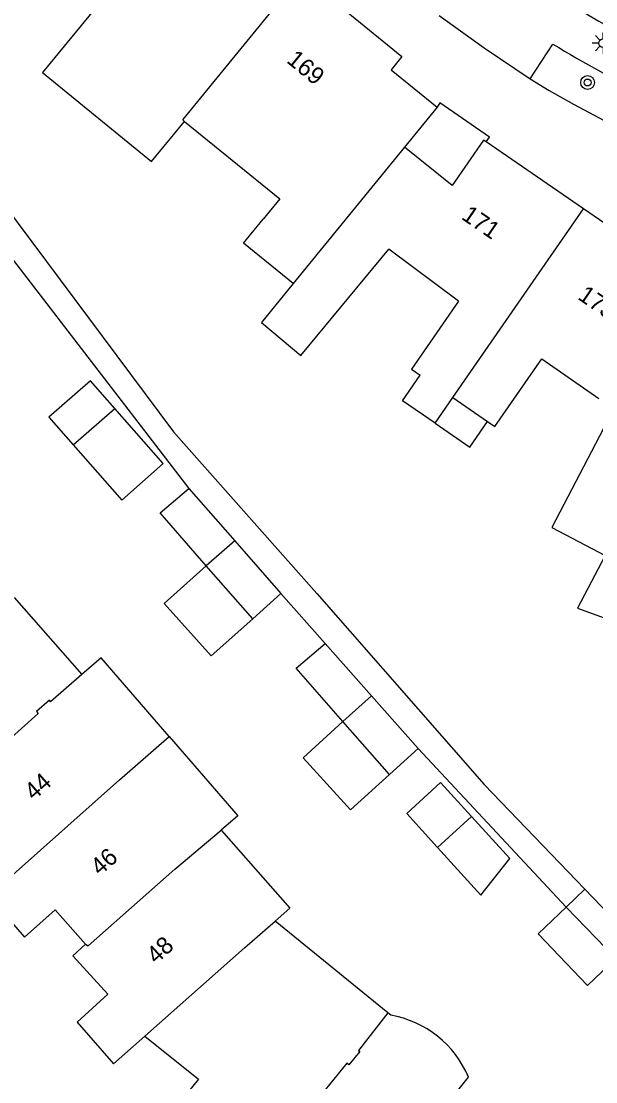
# Model space of a CAD drawing. Extents: x 126000 to 131009, y 393000 to 395500.
# Drawn here: x 130518.8 to 130552.1, y 394946.8 to 395008.4 of the extents above; entities that cross this region are included whole.
import ezdxf

# ---------------------------------------------------------------- set-up
doc = ezdxf.new("R2010")
doc.units = 0
for name, color, linetype in [('gg-afsc-erfafscheiding', 7, 'Continuous'), ('gg-anno-huisnummerreeks BGT', 7, 'Continuous'), ('gg-bbg-gedigitaliseerde bebouwing', 7, 'Continuous'), ('gg-bbg-gedigitaliseerde bijgebouw', 7, 'Continuous'), ('gg-bbg-hoofdgebouw', 7, 'Continuous'), ('gg-bbg-luifel en loopbrug', 7, 'Continuous'), ('gg-bbg-tussenscheiding', 7, 'Continuous'), ('gg-knt-verharding', 7, 'Continuous'), ('gt-grn-groengrens', 7, 'Continuous'), ('gt-symb-boom', 7, 'Continuous'), ('gt-symb-lichtmast', 7, 'Continuous')]:
    doc.layers.add(name, color=color, linetype=linetype)

# ---------------------------------------------------------------- blocks, each defined once
blk = doc.blocks.new('gt0-BOOM')
at = {"layer": 'gt-symb-boom'}
for radius in [0.4, 0.2]:
    blk.add_circle((0, 0), radius, dxfattribs=at)
blk = doc.blocks.new('gt0-LMAST')
at = {"layer": 'gt-symb-lichtmast'}
for p, q in [((-0.005, 0.246), (-0.005, 0.621)), ((-0.182, 0.173), (-0.447, 0.438)), ((0.172, 0.173), (0.437, 0.438)), ((-0.255, -0.004), (-0.63, -0.004)), ((-0.182, -0.181), (-0.447, -0.446)), ((-0.005, -0.254), (-0.005, -0.629)), ((0.437, -0.446), (0.172, -0.181)), ((0.245, -0.004), (0.62, -0.004))]:
    blk.add_line(p, q, dxfattribs=at)
blk.add_circle((-0.005, -0.004), 0.25, dxfattribs=at)

msp = doc.modelspace()

# ---------------------------------------------------------------- linework, layer by layer
at = {"layer": 'gg-afsc-erfafscheiding'}
for p, q in [((130518.346, 394994.504), (130528.53, 394981.27)), ((130533.87, 394975.19), (130536.44, 394972.29)), ((130541.82, 394966.18), (130550.41, 394956.98))]:
    msp.add_line(p, q, dxfattribs=at)
msp.add_lwpolyline([(130516.105, 395000), (130527.64, 394984.57), (130535.94, 394975.18), (130545.66, 394964.1), (130551.495, 394958.025)], dxfattribs=at)
at = {"layer": 'gg-bbg-gedigitaliseerde bebouwing'}
for p, q in [((130544.17, 394992.15), (130540.12, 394995.16)), ((130542.822, 394985.06), (130543.849, 394986.548)), ((130543.849, 394986.548), (130545.855, 394985.166)), ((130518.391, 394974.945), (130522.308, 394970.49)), ((130540.074, 394950.844), (130533.525, 394956.169)), ((130540.238, 394950.71), (130540.074, 394950.844)), ((130542.346, 394944.153), (130544.751, 394947.111))]:
    msp.add_line(p, q, dxfattribs=at)
for points in [[(130520.035, 395005.423), (130526.358, 395000.255), (130528.27, 395002.58)], [(130528.27, 395002.58), (130533.8, 394998.09), (130532.84, 394996.91)], [(130534.583, 394993.171), (130531.704, 394995.514), (130532.84, 394996.91)], [(130534.583, 394993.171), (130532.73, 394990.91), (130535.03, 394988.99), (130540.12, 394995.16)], [(130544.17, 394992.15), (130541.44, 394988.21), (130541.946, 394987.861)], [(130545.855, 394985.166), (130546.27, 394984.88), (130549, 394988.8), (130552.32, 394986.5)], [(130542.822, 394985.06), (130540.92, 394986.372), (130541.946, 394987.861)], [(130527.375, 394966.888), (130523.428, 394971.457), (130522.308, 394970.49)], [(130527.375, 394966.888), (130531.358, 394962.279), (130530.393, 394961.445)], [(130530.393, 394961.445), (130534.383, 394956.927), (130533.525, 394956.169)]]:
    msp.add_lwpolyline(points, dxfattribs=at)
msp.add_arc((130539.183, 394944.759), 6.044, 22.90496, 79.95214, dxfattribs=at)
at = {"layer": 'gg-bbg-gedigitaliseerde bijgebouw'}
for p, q in [((130521.815, 394983.809), (130524.228, 394985.91)), ((130527.036, 394982.718), (130524.228, 394985.91)), ((130528.53, 394981.27), (130531.192, 394978.239)), ((130531.192, 394978.239), (130533.87, 394975.19)), ((130532.23, 394973.72), (130529.537, 394976.793)), ((130533.87, 394975.19), (130532.23, 394973.72)), ((130536.44, 394972.29), (130539.13, 394969.235)), ((130539.13, 394969.235), (130541.82, 394966.18)), ((130540.16, 394964.67), (130537.46, 394967.755)), ((130541.82, 394966.18), (130540.16, 394964.67)), ((130544.928, 394962.234), (130542.956, 394960.44)), ((130550.41, 394956.98), (130553.29, 394953.99))]:
    msp.add_line(p, q, dxfattribs=at)
for points in [[(130553.277, 394986.099), (130549.58, 394979.02), (130552.68, 394977.38)], [(130521.815, 394983.809), (130524.632, 394980.604), (130527.036, 394982.718)], [(130529.537, 394976.793), (130526.85, 394979.86), (130528.53, 394981.27)], [(130552.68, 394977.38), (130551.08, 394974.34), (130555.012, 394972.908), (130556.613, 394977.306), (130557.4, 394977.02)], [(130537.46, 394967.755), (130534.76, 394970.84), (130536.44, 394972.29)], [(130542.956, 394960.44), (130541.162, 394962.412), (130543.134, 394964.206), (130544.928, 394962.234)], [(130553.29, 394953.99), (130551.65, 394952.43), (130548.79, 394955.44), (130550.41, 394956.98)]]:
    msp.add_lwpolyline(points, dxfattribs=at)
at = {"layer": 'gg-bbg-hoofdgebouw'}
for p, q in [((130542.924, 395003.409), (130541.033, 395001.079)), ((130551.415, 394997.507), (130545.775, 395001.389)), ((130557.162, 394993.55), (130551.415, 394997.507))]:
    msp.add_line(p, q, dxfattribs=at)
for points in [[(130519.934, 395013.069), (130523.704, 395009.912), (130520.035, 395005.423)], [(130534.299, 395010.443), (130534.941, 395011.207), (130540.874, 395006.339), (130540.256, 395005.575), (130542.924, 395003.409)], [(130545.775, 395001.389), (130545.615, 395001.499), (130543.8, 394998.863), (130541.033, 395001.079)], [(130516.905, 394957.61), (130518.994, 394955.243), (130520.776, 394956.819), (130522.536, 394954.83)], [(130522.536, 394954.83), (130521.801, 394954.161), (130523.825, 394951.925), (130522.036, 394950.306), (130524.16, 394947.877), (130525.963, 394949.494)], [(130525.963, 394949.494), (130529.083, 394946.996), (130527.186, 394944.654), (130529.705, 394942.602)]]:
    msp.add_lwpolyline(points, dxfattribs=at)
at = {"layer": 'gg-bbg-luifel en loopbrug'}
for p, q in [((130544.928, 394962.234), (130547.14, 394959.802)), ((130550.41, 394956.98), (130551.495, 394958.025))]:
    msp.add_line(p, q, dxfattribs=at)
for points in [[(130545.775, 395001.389), (130545.968, 395001.669), (130543.09, 395003.65), (130542.924, 395003.409)], [(130524.228, 394985.91), (130522.809, 394987.524), (130520.406, 394985.411), (130521.815, 394983.809)], [(130542.822, 394985.06), (130544.828, 394983.677), (130545.855, 394985.166)], [(130532.23, 394973.72), (130529.827, 394971.566), (130527.1, 394974.609), (130529.537, 394976.793)], [(130540.16, 394964.67), (130537.909, 394962.622), (130535.15, 394965.654), (130537.46, 394967.755)], [(130542.956, 394960.44), (130545.466, 394957.68), (130547.14, 394959.802)], [(130551.495, 394958.025), (130554.38, 394955.02), (130553.29, 394953.99)]]:
    msp.add_lwpolyline(points, dxfattribs=at)
at = {"layer": 'gg-bbg-tussenscheiding'}
for p, q in [((130541.033, 395001.079), (130534.583, 394993.171)), ((130543.849, 394986.548), (130551.415, 394997.507)), ((130531.192, 394978.239), (130529.537, 394976.793)), ((130537.46, 394967.755), (130539.13, 394969.235)), ((130527.72, 394959.19), (130530.393, 394961.445)), ((130531.76, 394954.61), (130533.525, 394956.169)), ((130525.963, 394949.494), (130531.76, 394954.61))]:
    msp.add_line(p, q, dxfattribs=at)
for points in [[(130528.27, 395002.58), (130528.17, 395002.67), (130534.43, 395010.34), (130534.299, 395010.443)], [(130522.308, 394970.49), (130520.5, 394968.9), (130520.43, 394968.99), (130519.68, 394968.33), (130519.78, 394968.21), (130514.75, 394963.71), (130514.858, 394963.557)], [(130516.905, 394957.61), (130524.5, 394964.36), (130527.375, 394966.888)], [(130522.536, 394954.83), (130522.68, 394954.73), (130527.72, 394959.19)], [(130540.074, 394950.844), (130538.36, 394948.67), (130538.44, 394948.6), (130537.81, 394947.82), (130537.69, 394947.92), (130533.42, 394942.67), (130533.302, 394942.745), (130532.662, 394941.973), (130532.771, 394941.883)]]:
    msp.add_lwpolyline(points, dxfattribs=at)
at = {"layer": 'gg-knt-verharding'}
msp.add_line((130548.322, 395005.051), (130549.641, 395007.069), dxfattribs=at)
msp.add_lwpolyline([(130543.042, 395008.729), (130545.65, 395006.844), (130548.322, 395005.051)], dxfattribs=at)
for centre, radius, start, end in [((130584.855, 395064.492), 64.849, 217.16814, 254.46544), ((130591.28, 395070.145), 64.986, 225.97128, 254.13763), ((130588.248, 395070.765), 74.482, 238.77915, 248.58581)]:
    msp.add_arc(centre, radius, start, end, dxfattribs=at)
at = {"layer": 'gt-grn-groengrens'}
msp.add_lwpolyline([(130548.322, 395005.051), (130549.429, 395004.378), (130550.84, 395003.581), (130554.36, 395001.7), (130557.28, 395000.392), (130559.896, 394999.292)], dxfattribs=at)

# ---------------------------------------------------------------- block references
at = {"layer": 'gt-symb-boom'}
msp.add_blockref('gt0-BOOM', (130551.661, 395004.839), dxfattribs=at)
at = {"layer": 'gt-symb-lichtmast'}
msp.add_blockref('gt0-LMAST', (130552.559, 395007.129), dxfattribs=at)

# ---------------------------------------------------------------- texts
at = {"layer": 'gg-anno-huisnummerreeks BGT'}
for s, rotation, p in [('169', 320.6, (130534.141, 395006.043)), ('171', 325.5, (130544.282, 394996.953)), ('173', 325.5, (130551.035, 394992.304)), ('44', 41.3, (130519.524, 394963.132)), ('46', 41.3, (130523.363, 394958.768)), ('48', 42.2, (130526.625, 394953.634))]:
    msp.add_text(s, height=1, rotation=rotation, dxfattribs=at).set_placement(p)

doc.saveas('drawing.dxf')
